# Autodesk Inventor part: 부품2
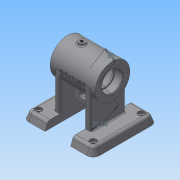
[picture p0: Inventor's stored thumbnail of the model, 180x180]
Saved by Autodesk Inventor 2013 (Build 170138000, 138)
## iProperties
Created: 2016-07
Part Number: 부품2
Material: Generic
Document SubType Name: Modeling
Designer: Administrator
Density: 1 g/cm^3
Author: Administrator
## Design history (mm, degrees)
sketch "스케치1"
  geometry: L1 (0, 0)-(70, 0); L2 (0, 0)-(0, 27); L3 (0, 27)-(70, 27); L4 (70, 27)-(70, 16); L5 (70, 16)-(58.3, 16); L6 (58, 15.7)-(58, 14); L7 (58, 14)-(56, 14); L8 (56, 14)-(56, 19); L9 (53, 22)-(17, 22); L10 (14, 19)-(14, 14); L11 (14, 14)-(12, 14); L12 (12, 14)-(12, 15.7); L13 (11.7, 16)-(0, 16); A1 r 0.3 centre (11.7, 15.7) between (12, 15.7) and (11.7, 16); A2 r 0.3 centre (58.3, 15.7) between (58.3, 16) and (58, 15.7); A3 r 3 centre (17, 19) between (17, 22) and (14, 19); A4 r 3 centre (53, 19) between (56, 19) and (53, 22); 3 further points
  constraints: 26 end point, 8 point on circle, 8 tangent, 7 parallel, 7 point on line, 5 perpendicular, 4 centre point, 2 equal radius, 1 horizontal
  dimensions: "d0" = 70 distance of L1.start L1.end; "d1" = 54 diameter of L3 L1; "d2" = 32 diameter of L5 L1; "d3" = 32 diameter of L13 L1; "d5" = 28 diameter of L11 L1; "d7" = 28 diameter of L7 L1; "d8" = 44 diameter of L9 L1; "d10" = 70 distance between parallel lines of L2 L4; "d12" = 12 distance of point (12, 16) L13.end; "d13" = 42 distance of point (56, 22) point (14, 22); "d15" = 2 distance of L10.end L11.end; "d16" = 2 distance of L6.end L7.end; "d17" = 0.3 radius of A1; "d18" = 3 radius of A3
revolve "회전1" sketch "스케치1" stored, may be unused: angle "d19" = 90 deg
chamfer "모따기1" distance "d20" = 1; stored, may be unused: second distance "d21" = 2, angle "d22" = 45 deg
sketch "스케치2" dims "d23" = 42
  geometry: C1 r 27 at (0, 0) reference; C2 r 17 at (0, 0) reference; C3 r 2 at (0, 21); 1 further point
  constraints: 1 centre point, 1 coincident, 1 vertical alignment, 2 other
  dimensions: "d25" = 0 horizontal distance of C1.centre C3.centre; "d26" = 4 diameter of C3
hole "구멍1" sketch "스케치2" at (0, 21) diameter "d27" = 3.242; stored, may be unused: countersink angle "d31" = 90 deg, drill point angle "d33" = 118 deg; dims "d28" = 8, "d29" = 4, "d30" = 2, "d32" = 10
sketch "스케치3" dims "d37" = 42
  geometry: C1 r 27 at (0, 0) reference; C2 r 17 at (0, 0) reference; C3 r 2 at (0, 21); 1 further point
  constraints: 1 centre point, 1 coincident, 1 vertical alignment, 2 other
  dimensions: "d39" = 0 horizontal distance of C3.centre C1.centre; "d40" = 4 diameter of C3
hole "구멍2" sketch "스케치3" at (0, 21) diameter "d41" = 3.242; stored, may be unused: countersink angle "d45" = 90 deg, drill point angle "d47" = 118 deg; dims "d42" = 8, "d43" = 4, "d44" = 2, "d46" = 10
node "작업 평면2"
  node "작업 평면1"
sketch "스케치4"
  geometry: C1 r 5 at (22, 0); 1 further point
  constraints: 1 centre point
  dimensions: "d53" = 22 distance of point (0, 0) C1.centre; "d54" = 0 vertical distance of C1.centre point (0, 0); "d55" = 10 diameter of C1
extrude "돌출1" join sketch "스케치4" stored distance "d56" = 10; taper "d57" = 0 deg
sketch "스케치5"
  geometry: C1 r 5 at (0, 0) reference; C2 r 3 at (0, 0); 1 further point
  constraints: 1 centre point, 1 coincident
  dimensions: "d58" = 6 diameter of C2
hole "구멍3" sketch "스케치5" at (0, 0) diameter "d60" = 5.188; stored, may be unused: countersink angle "d64" = 90 deg, drill point angle "d66" = 118 deg; dims "d61" = 8, "d62" = 4, "d63" = 2, "d65" = 10
fillet "모깎기1" dims "d67" = 2
node "작업 평면6"
  node "작업 평면5"
sketch "스케치11"
  geometry: L1 (-27, 0)-(-27, -58); L2 (27, 0)-(27, -58); L3 (27, -58)-(-27, -58); A1 r 27 centre (0, 0) between (-27, 0) and (27, 0) reference; 1 further point
  constraints: 6 end point, 2 point on circle, 2 tangent, 1 parallel, 1 perpendicular, 1 vertical
  dimensions: "d83" = 58 distance from line of L3 point (0, 0)
extrude "돌출4" join sketch "스케치11" distance "d84" = 8; taper "d85" = 0 deg
sketch "스케치12"
  geometry: L1 (-27, 0)-(-27, -58) reference; L2 (-27, -58)-(27, -58) reference; L3 (27, -58)-(27, 0) reference; L4 (-27, -58)-(-45.629, -58); L5 (-50, -70)-(50, -70); L6 (45.632, -58)-(27, -58); L7 (-50, -70)-(-50, -58); L8 (-50, -58)-(-45.629, -58); L9 (50, -70)-(50, -58); L10 (50, -58)-(45.632, -58); A1 r 27 centre (0, 0) between (-27, 0) and (27, 0) reference; 1 further point
  constraints: 14 end point, 5 perpendicular, 1 collinear, 1 parallel
  dimensions: "d86" = 70 distance from line of point (0, 0) L5; "d89" = 100 distance of L5.start L5.end; "d90" = 50 horizontal distance of point (0, 0) L5.end
extrude "돌출5" join sketch "스케치12" distance "d91" = 35; taper "d92" = 0 deg
node "작업 평면7"
fillet "모깎기2" dims "d94" = 10
feature "면 기울기1" dims angle "d95" = 20 deg
fillet "모깎기3" dims "d96" = 5
node "작업 평면8"
fillet "모깎기4" dims "d97" = 10
feature "면 기울기2" dims angle "d98" = 20 deg
fillet "모깎기5" dims "d99" = 5
node "작업 평면9"
sketch "스케치15"
  geometry: L1 (0, 0)-(88.355, 0); L2 (0, 0)-(25.441, 15.898); 1 further point
  constraints: 4 end point, 1 coincident, 1 horizontal
  dimensions: "d115" = 32 deg angle of L1 L2; "d116" = 30 distance of L1.start L2.end
node "작업 평면10"
sketch "스케치16"
  geometry: C1 r 6 at (0, 0); 4 further points
  constraints: 1 centre point, 1 coincident
  dimensions: "d117" = 12 diameter of C1
extrude "돌출8" join sketch "스케치16" stored distance "d119" = 8; taper "d120" = 0 deg
sketch "스케치17"
  geometry: C1 r 6 at (0, 0) reference; C2 r 3 at (0, 0); 2 further points
  constraints: 2 coincident, 1 centre point
  dimensions: "d144" = 6 diameter of C2
sketch "스케치18"
  geometry: L1 (-27, -13)-(-27, 67) reference; L2 (8, 77)-(-17, 77) reference; L3 (83, -13)-(83, 67) reference; L4 (-27, 27)-(83, 27); L5 (8, 77)-(47.76, 77); L6 (75.131, -13)-(79.83, -13) reference; L7 (79.83, -13)-(79.83, 67) reference; L8 (75.131, 67)-(79.83, 67) reference; L9 (75.131, 67)-(75.131, -13) reference; L10 (83, -13)-(83, 67) reference; L11 (48, -23)-(73, -23) reference; L12 (48, -23)-(48, 77) reference; L13 (48, 77)-(73, 77) reference; C1 r 5 at (-14.5, 64.5); C2 r 5 at (-14.5, -10.5); C3 r 4.528 at (65.654, 65.553); A1 r 10 centre (73, 67) between (83, 67) and (73, 77) reference; A2 r 10 centre (73, -13) between (73, -23) and (83, -13) reference; 1 further point
  constraints: 4 end point, 3 centre point, 2 midpoint, 1 parallel
  dimensions: "d125" = 10 diameter of C1; "d132" = 75 distance of C1.centre C2.centre; "d133" = 37.5 distance from line of L4 C2.centre; "d135" = 10 diameter of C2; "d136" = 12.5 distance from line of L1 C2.centre; "d137" = 12.5 distance from line of L1 C1.centre
extrude "돌출9" cut sketch "스케치18" distance "d126" = 4; taper "d127" = 0 deg
sketch "스케치20"
  geometry: C1 r 5 at (0, 0) reference; C2 r 3 at (0, 0); 1 further point
  constraints: 1 centre point, 1 coincident
  dimensions: "d138" = 6 diameter of C2
extrude "돌출11" cut sketch "스케치20" stored distance "d140" = 4; taper "d141" = 0 deg
node "작업 평면11"
hole "구멍4" sketch "스케치17" diameter "d146" = 5.188; stored, may be unused: countersink angle "d150" = 82 deg, drill point angle "d152" = 118 deg; dims "d147" = 8, "d148" = 3.023, "d149" = 2, "d151" = 8
fillet "모깎기6" dims "d153" = 2
fillet "모깎기7" dims "d154" = 2
sketch "스케치21"
  geometry: L1 (0, -27)-(-70, -27) reference; L2 (-55, -10.583)-(-55, -58) reference; L3 (-15, -10.583)-(-15, -58) reference; L4 (-55, -27)-(-15, -27); L5 (-15, -27)-(-15, -48); L6 (-15, -48)-(-55, -48); L7 (-55, -48)-(-55, -27); 1 further point
  constraints: 8 end point, 3 point on line, 2 parallel, 1 horizontal, 1 perpendicular
  dimensions: "d155" = 21 distance between parallel lines of L4 L6
extrude "돌출12" join sketch "스케치21" stored distance "d157" = 8; taper "d158" = 0 deg
sketch "스케치22"
  geometry: L1 (55, 48)-(15, 48) reference; L2 (74.5, 70)-(80.5, 70) reference; L3 (-10.5, 70)-(-4.5, 70) reference; L4 (0, -27)-(70, -27) reference; L5 (35, -27)-(35, 48); L6 (43, 34.5)-(27, 34.5); L7 (43, 41.5)-(27, 41.5); A1 r 3.5 centre (43, 38) between (43, 34.5) and (43, 41.5); A2 r 3.5 centre (27, 38) between (27, 34.5) and (27, 41.5); 1 further point
  constraints: 6 end point, 4 point on circle, 4 tangent, 2 centre point, 2 midpoint
  dimensions: "d160" = 7 diameter of A1; "d162" = 7 diameter of A2; "d163" = 32 distance from line of L2 A1.centre; "d164" = 32 distance from line of L3 A2.centre; "d165" = 23 dimension on A2 A1; "d166" = 11.5 dimension on A1 L5
extrude "돌출13" cut sketch "스케치22" stored distance "d167" = 8; taper "d168" = 0 deg
fillet "모깎기8" dims "d169" = 2
fillet "모깎기9" dims "d170" = 2
node "작업 평면12"
sketch "스케치23"
  geometry: L1 (14.261, 3.002)-(55.739, 3.002); L2 (55.739, 3.002)-(55.739, -3.002); L3 (55.739, -3.002)-(14.261, -3.002); L4 (14.261, -3.002)-(14.261, 3.002); L5 (14.261, 0)-(55.739, 0); L6 (35, 3.002)-(35, -3.002); 1 further point
  constraints: 4 end point, 4 midpoint, 2 other
  dimensions: "d172" = 35 distance from line of point (0, 0) L6; "d173" = 0 distance from line of point (0, 0) L5
feature "엠보싱1" sketch "스케치23" dims "d0" = 70, "d1" = 54, "d2" = 32, "d3" = 32, "d5" = 28, "d7" = 28, "d8" = 44, "d10" = 70, "d12" = 12, "d13" = 42, "d15" = 2, "d16" = 2, "d17" = 0.3, "d18" = 3, "d174" = 0.5, "d175" = 0
node "솔리드1"
pattern_circular "원형 패턴1" dims angle "d35" = 360 deg
pattern_circular "원형 패턴2" dims angle "d49" = 360 deg
mirror "대칭1"
mirror "대칭2"
mirror "대칭3"
node "투영된 루프1"
node "투영된 루프2"
other parameters: "d171" = -34.25
